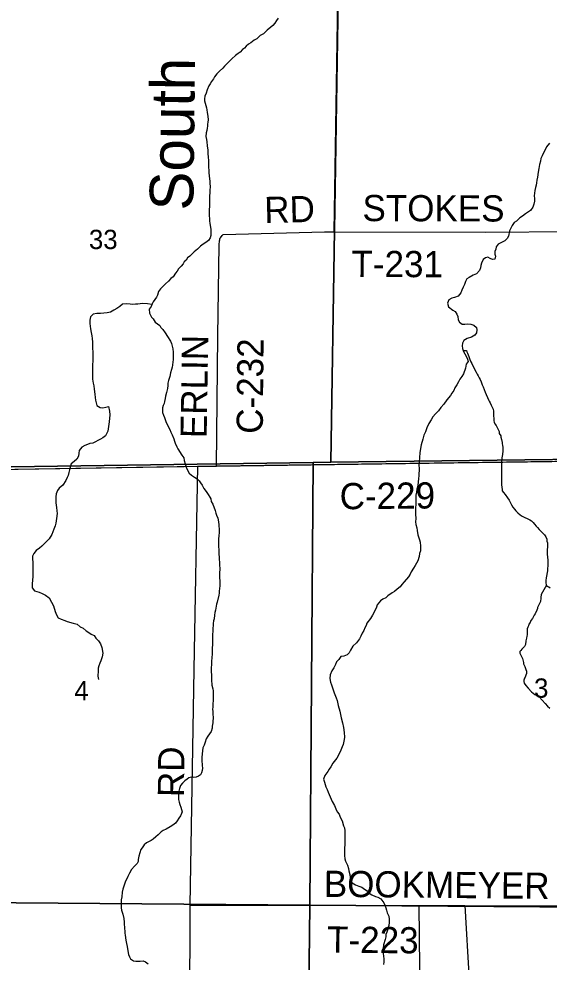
# Model space of a CAD drawing. Extents: x -8.5 to 18.7, y -20.3 to 7.
# Drawn here: x 4.267 to 6.568, y -1.005 to 3.087 of the extents above; entities that cross this region are included whole.
import ezdxf

# ---------------------------------------------------------------- set-up
doc = ezdxf.new("R2010")
doc.units = 0
for name, color, linetype in [('GM_X_Corporation', 7, 'Continuous'), ('GM_X_County_Road', 7, 'Continuous'), ('GM_X_County_Road_Text', 7, 'Continuous'), ('GM_X_Minor_River', 7, 'Continuous'), ('GM_X_Minor_River_Text', 7, 'Continuous'), ('GM_X_Section', 7, 'Continuous'), ('GM_X_Section_Text', 7, 'Continuous'), ('GM_X_Township', 7, 'Continuous'), ('GM_X_Township_Road', 7, 'Continuous'), ('GM_X_Township_Road_Text', 7, 'Continuous')]:
    doc.layers.add(name, color=color, linetype=linetype)

msp = doc.modelspace()

# ---------------------------------------------------------------- linework, layer by layer
at = {"layer": 'GM_X_Corporation'}
for points in [[(3.6318, 1.1236), (5.043, 1.1473), (5.1251, 1.1484), (7.5383, 1.181), (7.59, 1.1818), (9.5569, 1.2131), (11.5871, 1.2389), (11.6132, 2.2462), (11.64, 3.2551), (11.6653, 4.2586), (11.6686, 4.5917), (11.6689, 4.6186), (11.6732, 5.0475), (11.7049, 6.938), (-0.1911, 6.938)], [(6.0195, -2.1051), (6.0042, -0.7588), (6.2025, -0.7592), (6.2213, -1.0838)]]:
    msp.add_lwpolyline(points, dxfattribs=at)
at = {"layer": 'GM_X_County_Road'}
for p, q in [((4.9846, 1.1452), (5.0434, 1.1462)), ((5.0285, 0.2644), (5.0434, 1.1462)), ((5.0434, 1.1462), (5.1255, 1.1473)), ((5.1255, 1.1473), (6.0476, 1.1597)), ((3.6322, 1.1225), (4.9846, 1.1452))]:
    msp.add_line(p, q, dxfattribs=at)
for points in [[(5.1255, 1.1473), (5.1307, 1.71), (5.1363, 2.1065), (5.1381, 2.1247), (5.1389, 2.1285), (5.1398, 2.1338), (5.1421, 2.1376), (5.1491, 2.1474), (5.1537, 2.1511), (5.5936, 2.163), (5.6353, 2.1639), (5.6522, 3.168), (5.6659, 4.3348)], [(6.0476, 1.1597), (7.5387, 1.1799), (7.5905, 1.1807)], [(5.0013, -1.7027), (5.0019, -1.6852), (5.0045, -1.5114), (5.0068, -1.3109), (5.0093, -1.0879), (5.0109, -0.8927), (5.0112, -0.7576), (5.0285, 0.2644)]]:
    msp.add_lwpolyline(points, dxfattribs=at)
at = {"layer": 'GM_X_Minor_River'}
for points in [[(5.3929, 3.0899), (5.3852, 3.0801), (5.3783, 3.0688), (5.3698, 3.0582), (5.3606, 3.0515), (5.3445, 3.0387), (5.3292, 3.023), (5.3147, 3.0148), (5.3001, 3.0005), (5.2879, 2.9953), (5.2741, 2.9841), (5.2634, 2.9781), (5.2535, 2.9684), (5.2465, 2.9601), (5.2374, 2.9549), (5.2281, 2.9428), (5.219, 2.9376), (5.2075, 2.9286), (5.1921, 2.9136), (5.1791, 2.9016), (5.1707, 2.8933), (5.1599, 2.882), (5.1522, 2.8738), (5.1377, 2.8603), (5.1269, 2.8482), (5.1169, 2.8362), (5.1123, 2.8279), (5.1038, 2.8151), (5.0976, 2.806), (5.0922, 2.7962), (5.0851, 2.7788), (5.0804, 2.7652), (5.0742, 2.7516), (5.0726, 2.741), (5.0725, 2.7319), (5.0791, 2.7113), (5.0812, 2.7014), (5.0826, 2.6923), (5.0848, 2.6817), (5.0876, 2.6657), (5.0882, 2.6497), (5.0873, 2.6391), (5.0865, 2.63), (5.0856, 2.6217), (5.0848, 2.6126), (5.0824, 2.6035), (5.08, 2.5929), (5.0791, 2.5777), (5.0812, 2.5633), (5.0826, 2.5534), (5.0839, 2.5367), (5.0875, 2.5184), (5.0881, 2.5047), (5.0894, 2.4865), (5.09, 2.4743), (5.0898, 2.4523), (5.0904, 2.4417), (5.0911, 2.4318), (5.0917, 2.4189), (5.093, 2.406), (5.0944, 2.3938), (5.0958, 2.3839), (5.0964, 2.3718), (5.0971, 2.3619), (5.0968, 2.3414), (5.096, 2.3323), (5.0951, 2.3194), (5.0949, 2.3012), (5.094, 2.2913), (5.0934, 2.2427), (5.0946, 2.2108), (5.096, 2.1994), (5.1003, 2.1751), (5.1009, 2.1652)], [(6.5695, 2.5481), (6.5572, 2.5322), (6.5494, 2.5156), (6.544, 2.5058), (6.5378, 2.4937), (6.5331, 2.4809), (6.5307, 2.4703), (6.5267, 2.4559), (6.5235, 2.4377), (6.521, 2.4218)], [(6.521, 2.4218), (6.5178, 2.4006), (6.5153, 2.3877), (6.5137, 2.3763), (6.5121, 2.3665), (6.5089, 2.3559), (6.5057, 2.3422), (6.5048, 2.3316), (6.5039, 2.3202), (6.5046, 2.3073), (6.5044, 2.2967), (6.502, 2.2838), (6.4973, 2.2702), (6.4873, 2.2566), (6.4659, 2.2409), (6.4529, 2.2312), (6.4406, 2.2245), (6.4268, 2.2095), (6.4161, 2.2035), (6.4084, 2.1914), (6.4014, 2.1771), (6.3967, 2.1673), (6.3919, 2.1453), (6.3865, 2.134), (6.3758, 2.125), (6.3582, 2.1153), (6.3475, 2.1101), (6.3383, 2.0988), (6.3367, 2.0889), (6.3328, 2.0776), (6.3326, 2.067), (6.3363, 2.0571), (6.3331, 2.0449), (6.3233, 2.0435), (6.3127, 2.0474), (6.3021, 2.0529), (6.2922, 2.0499), (6.2823, 2.044), (6.2745, 2.0273), (6.2714, 2.0168), (6.2705, 2.0069), (6.2666, 1.9963), (6.2528, 1.9813), (6.239, 1.9753), (6.2215, 1.9657), (6.2108, 1.9589), (6.2053, 1.9484), (6.2014, 1.9355), (6.196, 1.9234), (6.1897, 1.9106), (6.185, 1.8985), (6.1735, 1.8849), (6.1583, 1.8783), (6.1461, 1.8754), (6.1331, 1.8687), (6.1269, 1.8536), (6.1313, 1.8383), (6.15, 1.8229), (6.1606, 1.8175), (6.1681, 1.8068), (6.1717, 1.7961), (6.1738, 1.7809), (6.1798, 1.771), (6.1911, 1.7633), (6.2032, 1.7631), (6.2139, 1.7646), (6.229, 1.7629), (6.2419, 1.7589), (6.2539, 1.7482), (6.2553, 1.7383), (6.2529, 1.7247), (6.2459, 1.7149), (6.2314, 1.7067), (6.2124, 1.7008), (6.1986, 1.6918), (6.1924, 1.6797), (6.1915, 1.6691), (6.1929, 1.6577), (6.1973, 1.644), (6.2033, 1.6341), (6.2077, 1.6242), (6.2144, 1.6104), (6.2165, 1.6005), (6.2088, 1.5885), (6.2048, 1.5718), (6.197, 1.5476), (6.1893, 1.5355), (6.1815, 1.5242), (6.1746, 1.5129), (6.1684, 1.4993), (6.1591, 1.4865), (6.1544, 1.4752), (6.1467, 1.4631), (6.1405, 1.4533), (6.1244, 1.4345), (6.1113, 1.4156), (6.0989, 1.4006), (6.0882, 1.3863), (6.0759, 1.3735), (6.0644, 1.3607), (6.0559, 1.3479)], [(5.1009, 2.1652), (5.1008, 2.1569), (5.1007, 2.147), (5.0976, 2.1372), (5.0906, 2.1251), (5.0791, 2.1176), (5.0669, 2.1094), (5.0562, 2.1012), (5.0431, 2.0876), (5.0286, 2.0764), (5.0202, 2.0697), (5.0087, 2.0584), (4.9995, 2.0501), (4.994, 2.0403), (4.9848, 2.0336), (4.9802, 2.0245), (4.9717, 2.014), (4.9602, 2.0027), (4.9548, 1.9929), (4.9471, 1.9839), (4.9363, 1.9688), (4.9271, 1.9613), (4.9164, 1.95), (4.9041, 1.9373), (4.8926, 1.926), (4.8826, 1.9155), (4.8734, 1.9042), (4.8686, 1.8883), (4.8647, 1.88), (4.8509, 1.8596), (4.8454, 1.8506), (4.8415, 1.84), (4.833, 1.8272), (4.8344, 1.8105), (4.8425, 1.7937), (4.85, 1.7852), (4.859, 1.7715), (4.8785, 1.7568), (4.8837, 1.7477), (4.892, 1.7392), (4.9024, 1.7255), (4.9129, 1.7086), (4.9248, 1.6888), (4.9292, 1.6789), (4.9329, 1.6674), (4.9358, 1.6553), (4.9371, 1.6408), (4.9368, 1.6082), (4.9359, 1.5998), (4.9342, 1.5854), (4.9326, 1.5763), (4.9302, 1.5657), (4.9255, 1.5514), (4.9223, 1.5362), (4.9168, 1.5188), (4.9144, 1.5067), (4.9135, 1.4968), (4.9118, 1.4839), (4.9086, 1.4657), (4.9038, 1.4506), (4.9022, 1.4408), (4.8998, 1.4279), (4.8974, 1.4188), (4.8935, 1.4097), (4.8904, 1.3991), (4.8909, 1.3794), (4.8946, 1.368), (4.8998, 1.358), (4.9049, 1.3398), (4.9116, 1.3275), (4.9219, 1.3062), (4.9271, 1.2947), (4.933, 1.2825), (4.9397, 1.2657), (4.9433, 1.2551), (4.9463, 1.2459), (4.9529, 1.2307), (4.9566, 1.2215), (4.9745, 1.194), (4.9827, 1.1833), (4.9849, 1.1711), (4.9893, 1.1574), (4.9914, 1.1483), (4.9951, 1.1383), (5.007, 1.117), (5.016, 1.1078), (5.0296, 1.0985), (5.0409, 1.0915), (5.0491, 1.0831), (5.0551, 1.0747), (5.0626, 1.064), (5.0707, 1.0502), (5.0805, 1.0372), (5.0894, 1.0242), (5.0961, 1.0128), (5.1006, 1.0044), (5.102, 0.9937), (5.1094, 0.9815), (5.119, 0.9541), (5.1219, 0.9426), (5.1256, 0.9335)], [(4.8443, 1.8475), (4.825, 1.8516), (4.8037, 1.8518), (4.784, 1.8497), (4.7733, 1.8491), (4.762, 1.8477), (4.7506, 1.8493), (4.7362, 1.851), (4.7172, 1.8489), (4.705, 1.8392), (4.6927, 1.831), (4.6797, 1.8235), (4.6645, 1.8153), (4.65, 1.8117), (4.6363, 1.8103), (4.6212, 1.809), (4.606, 1.8084), (4.5893, 1.8063), (4.5785, 1.7942), (4.5753, 1.7806), (4.5759, 1.7654), (4.5787, 1.7426), (4.5815, 1.7259), (4.5836, 1.7122), (4.585, 1.7008), (4.5864, 1.6848), (4.5876, 1.6643), (4.5888, 1.6362), (4.5879, 1.6225), (4.5877, 1.6043), (4.5868, 1.5861), (4.5863, 1.5444), (4.5876, 1.5238), (4.5896, 1.5064), (4.5926, 1.4957), (4.5947, 1.4813), (4.5967, 1.4592), (4.5988, 1.444), (4.6002, 1.4326), (4.6023, 1.4212), (4.6052, 1.4098), (4.6203, 1.4013), (4.6324, 1.4004), (4.6454, 1.4025), (4.656, 1.4054), (4.6611, 1.3856), (4.6624, 1.3689), (4.659, 1.3386), (4.6533, 1.2992), (4.6486, 1.2894), (4.6439, 1.2788), (4.6317, 1.2698), (4.6218, 1.2631), (4.5882, 1.2467), (4.576, 1.2446), (4.5646, 1.2409), (4.5539, 1.2357), (4.5402, 1.229), (4.5294, 1.2147), (4.5278, 1.2033), (4.5261, 1.1897), (4.5184, 1.1769), (4.5076, 1.1664), (4.4946, 1.1574), (4.4875, 1.1301), (4.4843, 1.1188), (4.4819, 1.1067), (4.4772, 1.0968), (4.471, 1.084), (4.4587, 1.0644), (4.4426, 1.0516), (4.4349, 1.0411), (4.4286, 1.026), (4.4277, 1.0131), (4.4276, 1.0009), (4.4282, 0.9873), (4.431, 0.9667), (4.4316, 0.9531), (4.433, 0.9417), (4.4312, 0.9189), (4.428, 0.9), (4.4255, 0.8871), (4.4193, 0.8727), (4.4146, 0.8621), (4.4107, 0.85), (4.3991, 0.8319), (4.3876, 0.8199), (4.3768, 0.8094), (4.3676, 0.7996), (4.3577, 0.7914), (4.3431, 0.7809), (4.3324, 0.7681), (4.3269, 0.7568), (4.326, 0.7439), (4.3274, 0.7287), (4.3279, 0.7074), (4.3274, 0.668), (4.3248, 0.6361), (4.3254, 0.6194), (4.3351, 0.6056), (4.3555, 0.5993)], [(6.1957, 1.649), (6.2098, 1.6488), (6.2114, 1.6427), (6.2145, 1.6366), (6.2198, 1.623), (6.2237, 1.6101), (6.2283, 1.5995), (6.2329, 1.5919), (6.236, 1.5851), (6.2421, 1.5752), (6.2467, 1.5646), (6.2521, 1.5548), (6.2567, 1.5464), (6.2605, 1.5388), (6.2651, 1.5305), (6.2689, 1.5229), (6.2728, 1.5123), (6.2782, 1.5002), (6.2828, 1.4903), (6.2866, 1.4789), (6.2912, 1.4683), (6.2958, 1.457), (6.3012, 1.4448), (6.3051, 1.435), (6.3081, 1.4281), (6.312, 1.4213), (6.3166, 1.4107), (6.3212, 1.4024), (6.325, 1.394), (6.3266, 1.3849), (6.3274, 1.3758), (6.3274, 1.3637), (6.3282, 1.3546), (6.3291, 1.3439), (6.3306, 1.3378), (6.3329, 1.331), (6.3383, 1.3227), (6.3459, 1.309), (6.3513, 1.2977), (6.3521, 1.2886), (6.3582, 1.278), (6.359, 1.2726), (6.3614, 1.262), (6.3645, 1.2491), (6.3653, 1.243), (6.366, 1.2377), (6.3669, 1.2271), (6.3676, 1.2218), (6.3677, 1.2134), (6.3655, 1.1975), (6.3633, 1.1823), (6.3618, 1.1655), (6.3612, 1.1526), (6.362, 1.1351), (6.3613, 1.1275), (6.3613, 1.1207), (6.3621, 1.1108), (6.3622, 1.104), (6.3615, 1.0827), (6.3616, 1.066), (6.364, 1.0455), (6.3648, 1.0394), (6.3709, 1.0326), (6.377, 1.0243), (6.3877, 1.0091), (6.3946, 0.9985), (6.3992, 0.9902), (6.4045, 0.9796), (6.4114, 0.969), (6.4183, 0.9599), (6.4237, 0.9531), (6.4321, 0.9448), (6.4427, 0.9357), (6.4519, 0.9297), (6.4625, 0.9244), (6.4724, 0.9191), (6.4846, 0.9131), (6.4914, 0.9094), (6.4991, 0.9026), (6.5052, 0.8957), (6.5121, 0.8867), (6.5182, 0.8806), (6.5258, 0.8723), (6.535, 0.8617), (6.5426, 0.8541), (6.5487, 0.8488), (6.554, 0.8405), (6.5579, 0.8299), (6.5587, 0.8215), (6.561, 0.8147), (6.5611, 0.7965), (6.5596, 0.7836), (6.5597, 0.7744), (6.5605, 0.7653), (6.5613, 0.7524), (6.5622, 0.7388), (6.5623, 0.7129), (6.5616, 0.7038), (6.5608, 0.6985), (6.5609, 0.6932), (6.5594, 0.6848)], [(6.0559, 1.3479), (6.0458, 1.3313), (6.0373, 1.3124), (6.0317, 1.295), (6.0247, 1.2807), (6.0208, 1.264), (6.0137, 1.2398), (6.0097, 1.2239), (6.0072, 1.2049), (6.0054, 1.1837), (6.0045, 1.1647), (6.0035, 1.1488), (6.0042, 1.1389), (6.004, 1.126), (6.0031, 1.1162), (6.003, 1.104), (6.0021, 1.0941), (5.9996, 1.076), (5.9988, 1.0661), (5.9971, 1.0562), (5.9948, 1.0464), (5.9931, 1.0335), (5.9907, 1.0214), (5.9898, 1.0085), (5.989, 0.9379), (5.9895, 0.9197), (5.9886, 0.9052), (5.99, 0.8938), (5.9936, 0.8794), (5.9958, 0.868), (5.9993, 0.8489), (6.0059, 0.8269), (6.0088, 0.817), (6.0109, 0.7995), (6.0099, 0.779), (6.006, 0.7676), (6.0043, 0.7548), (5.9988, 0.7366), (5.9864, 0.7155), (5.9802, 0.7034), (5.9702, 0.6875), (5.9648, 0.6777), (5.9586, 0.6664), (5.9393, 0.6446), (5.9294, 0.6333), (5.9224, 0.6228), (5.9086, 0.613), (5.8979, 0.6033), (5.8872, 0.5966), (5.8681, 0.5846), (5.8596, 0.5748), (5.8474, 0.5689), (5.8367, 0.5622), (5.8229, 0.5456), (5.819, 0.535), (5.8151, 0.5252), (5.8019, 0.5003), (5.7934, 0.4852), (5.778, 0.4656), (5.7741, 0.4551), (5.7686, 0.4452), (5.764, 0.4339), (5.7578, 0.4218), (5.7508, 0.4097), (5.7453, 0.3977), (5.7322, 0.3796), (5.7161, 0.3661), (5.7068, 0.3487), (5.7014, 0.3366), (5.6914, 0.3276), (5.6777, 0.3225), (5.6648, 0.3211), (5.6563, 0.3075), (5.6456, 0.297), (5.6409, 0.2864), (5.6347, 0.2721), (5.6254, 0.2593), (5.6176, 0.2411), (5.6174, 0.2259), (5.6195, 0.21), (5.6239, 0.1978), (5.6291, 0.181), (5.6357, 0.1635), (5.6446, 0.1421), (5.6482, 0.1299), (5.6533, 0.1079), (5.6606, 0.0835), (5.6663, 0.0553), (5.6721, 0.0325), (5.6765, 0.0135), (5.6785, -0.0086), (5.6805, -0.0291), (5.6789, -0.0397), (5.6749, -0.0609), (5.6702, -0.0707), (5.6647, -0.0859), (5.6585, -0.0979), (5.6469, -0.1198), (5.6299, -0.1424), (5.6214, -0.1575), (5.6145, -0.1681)], [(5.1256, 0.9335), (5.1315, 0.9205), (5.1336, 0.9045), (5.1349, 0.8916), (5.1362, 0.8696), (5.1361, 0.8582), (5.1352, 0.8445), (5.1343, 0.8316), (5.1339, 0.7975), (5.1345, 0.7838), (5.135, 0.7656), (5.1364, 0.7511), (5.137, 0.742), (5.1376, 0.7299), (5.1383, 0.717), (5.1389, 0.7025), (5.1378, 0.6805), (5.1384, 0.6615), (5.139, 0.6486), (5.1396, 0.6388), (5.1395, 0.6274), (5.1386, 0.6152), (5.137, 0.6046), (5.1361, 0.5955), (5.1345, 0.5864), (5.1273, 0.5569), (5.1249, 0.5478), (5.1233, 0.5395), (5.1217, 0.5311), (5.1201, 0.5213), (5.1185, 0.5122), (5.1161, 0.5008), (5.1144, 0.4849), (5.1127, 0.4758), (5.1111, 0.4637), (5.1102, 0.4546), (5.1094, 0.4447), (5.1085, 0.4356), (5.1084, 0.4273), (5.1075, 0.4189), (5.1073, 0.3946), (5.1079, 0.3817), (5.1077, 0.3703), (5.1069, 0.3597), (5.106, 0.3461), (5.1058, 0.3354), (5.1041, 0.3127), (5.1032, 0.3036), (5.1026, 0.2542), (5.1032, 0.2406), (5.103, 0.2193), (5.105, 0.1965), (5.1086, 0.1805), (5.11, 0.1722), (5.1112, 0.1448), (5.1111, 0.1319), (5.1094, 0.1145), (5.1085, 0.1016), (5.1076, 0.0917), (5.109, 0.0826), (5.1097, 0.0742), (5.1102, 0.053), (5.1093, 0.0408), (5.1092, 0.0325), (5.1068, 0.0188), (5.1059, 0.0105), (5.1012, -0.0046), (5.095, -0.0144), (5.0873, -0.025), (5.0803, -0.0363), (5.0756, -0.0507), (5.0709, -0.0635), (5.0662, -0.0756), (5.0646, -0.0885), (5.0612, -0.1158), (5.0618, -0.1295), (5.0631, -0.1515), (5.0637, -0.1637), (5.0628, -0.1743), (5.0605, -0.1834), (5.0558, -0.1924), (5.0466, -0.1984), (5.0367, -0.2021), (5.0253, -0.2035), (5.017, -0.2034), (5.0056, -0.2063), (4.9972, -0.2116), (4.9872, -0.2183), (4.978, -0.228), (4.9695, -0.2393), (4.9641, -0.2514), (4.9609, -0.2628), (4.96, -0.278), (4.9599, -0.2878), (4.9605, -0.2992), (4.9626, -0.3114), (4.9656, -0.3213), (4.97, -0.3335), (4.9737, -0.3426), (4.9758, -0.3525), (4.9735, -0.3609)], [(6.5594, 0.6848), (6.5564, 0.6696), (6.5557, 0.6627), (6.5542, 0.6506), (6.5543, 0.6384), (6.5551, 0.6331), (6.5589, 0.6263), (6.5665, 0.6225), (6.5734, 0.6188)], [(6.5569, 0.6299), (6.5342, 0.5899), (6.5331, 0.577), (6.5322, 0.5694), (6.5306, 0.5641), (6.5305, 0.5588), (6.5273, 0.5506), (6.5186, 0.534), (6.5177, 0.5287), (6.5146, 0.5212), (6.5082, 0.5054), (6.5035, 0.5002), (6.4956, 0.4852), (6.4894, 0.4777), (6.4854, 0.4687), (6.4807, 0.4612), (6.4791, 0.4544), (6.4759, 0.4484), (6.4735, 0.4409), (6.4726, 0.4356), (6.4724, 0.4227), (6.473, 0.4151), (6.4721, 0.4098), (6.4704, 0.4), (6.4679, 0.3894), (6.4653, 0.3727), (6.4613, 0.3645), (6.4551, 0.3585), (6.4497, 0.3533), (6.4451, 0.3473), (6.4419, 0.3421), (6.441, 0.3353), (6.449, 0.3207), (6.4534, 0.3115), (6.4576, 0.2947), (6.4575, 0.2894), (6.4625, 0.2772), (6.4676, 0.2642), (6.4697, 0.2566), (6.4702, 0.2475), (6.4678, 0.2399), (6.4638, 0.2317), (6.4622, 0.2264), (6.459, 0.2181), (6.4582, 0.2128), (6.4595, 0.2052), (6.4669, 0.1952), (6.4772, 0.1828), (6.4913, 0.1681), (6.507, 0.1564), (6.5249, 0.1455), (6.5516, 0.1176), (6.5619, 0.1053), (6.5708, 0.0968)], [(4.3555, 0.5993), (4.3691, 0.5946), (4.3834, 0.5876), (4.3992, 0.5761), (4.4096, 0.5562), (4.4178, 0.5402), (4.4251, 0.5166), (4.431, 0.5021), (4.4384, 0.4891), (4.4505, 0.4822), (4.4671, 0.4767), (4.4769, 0.472), (4.5034, 0.4656), (4.5201, 0.4617), (4.5328, 0.4501), (4.5464, 0.4439), (4.5599, 0.4316), (4.5712, 0.4254), (4.5818, 0.4177), (4.5938, 0.4115), (4.6021, 0.4001), (4.6126, 0.3893), (4.6223, 0.3763), (4.6274, 0.3603), (4.6317, 0.336), (4.6292, 0.32), (4.6229, 0.3019), (4.619, 0.2921), (4.6143, 0.2807), (4.612, 0.2709), (4.6111, 0.2587), (4.6108, 0.2352), (4.6133, 0.2214)], [(5.6145, -0.1681), (5.6083, -0.1779), (5.5944, -0.1959), (5.5897, -0.2118), (5.5933, -0.2248), (5.5992, -0.2453), (5.6051, -0.256), (5.6095, -0.2682), (5.6176, -0.288), (5.6273, -0.3079), (5.6369, -0.3262), (5.6428, -0.3399), (5.648, -0.3529), (5.6577, -0.3636), (5.6622, -0.3758), (5.6703, -0.3926), (5.6761, -0.4132), (5.6798, -0.4231), (5.6812, -0.436), (5.6818, -0.4474), (5.6814, -0.4823), (5.682, -0.4975), (5.6811, -0.5074), (5.6807, -0.5431), (5.6813, -0.5567), (5.6843, -0.5666), (5.6932, -0.5842), (5.6975, -0.5994), (5.6997, -0.6093), (5.7041, -0.6253), (5.7054, -0.6375), (5.7061, -0.6481), (5.7143, -0.6611), (5.7278, -0.6703), (5.7422, -0.6751), (5.755, -0.6797), (5.7678, -0.689), (5.7784, -0.6952), (5.7881, -0.7059), (5.7987, -0.7129), (5.8153, -0.7206), (5.8251, -0.723), (5.8387, -0.7307), (5.8506, -0.7483), (5.8558, -0.7583), (5.8595, -0.7689), (5.8631, -0.7804), (5.866, -0.791), (5.8727, -0.8063), (5.8748, -0.8192), (5.8747, -0.8329), (5.873, -0.8458), (5.8683, -0.8616), (5.8643, -0.8745), (5.8597, -0.8851), (5.8595, -0.895), (5.8564, -0.9071), (5.85, -0.9305), (5.8476, -0.9457), (5.8482, -0.9578), (5.8488, -0.9677), (5.8509, -0.9913), (5.8507, -1.0034), (5.8498, -1.0148)], [(4.9735, -0.3609), (4.9688, -0.3707), (4.9619, -0.3805), (4.9549, -0.3925), (4.9472, -0.4023), (4.9349, -0.4113), (4.9242, -0.418), (4.9067, -0.4285), (4.8937, -0.4344), (4.8853, -0.4404), (4.8723, -0.4524), (4.8615, -0.4621), (4.85, -0.4719), (4.8416, -0.4779), (4.8325, -0.4823), (4.821, -0.4883), (4.8111, -0.4958), (4.8018, -0.5086), (4.7972, -0.5169), (4.7925, -0.5312), (4.7878, -0.5449), (4.7853, -0.5593), (4.7852, -0.5684), (4.7806, -0.5774), (4.769, -0.5895), (4.7567, -0.603), (4.7475, -0.6196), (4.7397, -0.6339), (4.7358, -0.6445), (4.7304, -0.6543), (4.7249, -0.6717), (4.7186, -0.6884), (4.7154, -0.7012), (4.7137, -0.7217), (4.712, -0.7346), (4.711, -0.7543), (4.7108, -0.7695), (4.7122, -0.7802), (4.7181, -0.7977), (4.7224, -0.8159), (4.7238, -0.8311), (4.7244, -0.8433), (4.7251, -0.8517), (4.7257, -0.8608), (4.7271, -0.8699), (4.7278, -0.879), (4.7292, -0.8881), (4.732, -0.9094), (4.7349, -0.9246), (4.737, -0.9376), (4.7406, -0.9566), (4.7434, -0.9726), (4.7479, -0.9825), (4.7516, -0.9909), (4.7643, -0.9994), (4.7757, -1.001), (4.7848, -1.0011), (4.7939, -1.0004), (4.8068, -0.9998), (4.8166, -1.0045), (4.8287, -1.0122)]]:
    msp.add_lwpolyline(points, dxfattribs=at)
at = {"layer": 'GM_X_Section'}
for points in [[(7.6532, 3.1997), (7.5973, 1.189), (7.5458, 1.1869), (5.621, 1.1642), (5.6525, 3.1789)], [(5.6525, 3.1789), (5.621, 1.1642), (5.5445, 1.1632), (3.628, 1.1349), (3.6457, 3.1367)], [(7.5458, 1.1869), (7.5243, -0.7725), (5.5303, -0.7575), (5.5445, 1.1632), (5.621, 1.1642)], [(5.5445, 1.1632), (5.5303, -0.7575), (3.5254, -0.7421), (3.5552, 1.1316), (3.628, 1.1349)], [(5.5303, -0.7575), (5.5072, -2.7563), (3.5091, -2.759), (3.5254, -0.7421)], [(7.5243, -0.7725), (7.4906, -2.7325), (5.5072, -2.7563), (5.5303, -0.7575)]]:
    msp.add_lwpolyline(points, close=True, dxfattribs=at)
at = {"layer": 'GM_X_Township'}
msp.add_lwpolyline([(3.6318, 1.1236), (5.043, 1.1473), (5.1251, 1.1484), (7.5383, 1.181), (7.59, 1.1818), (9.5569, 1.2131), (11.5871, 1.2389), (11.5625, -0.7587), (11.5622, -0.7805), (11.5527, -2.1798)], dxfattribs=at)
at = {"layer": 'GM_X_Township_Road'}
for p, q in [((5.0112, -0.7576), (6.0047, -0.7599)), ((6.0047, -0.7599), (6.203, -0.7603)), ((6.203, -0.7603), (7.5325, -0.7633))]:
    msp.add_line(p, q, dxfattribs=at)
msp.add_lwpolyline([(5.6353, 2.1639), (6.2929, 2.1617), (6.6703, 2.1655), (6.924, 2.1827), (7.6182, 2.1915)], dxfattribs=at)

# ---------------------------------------------------------------- texts
at = {"layer": 'GM_X_County_Road_Text'}
for s, rotation, p in [('RD', 1.4816, (5.3337, 2.2011)), ('ERLIN', 89.0651, (5.0822, 1.2676)), ('C-232', 89.4494, (5.3256, 1.2866)), ('C-229', 0.5511, (5.66, 0.9594)), ('RD', 89.5063, (4.9839, -0.2894))]:
    msp.add_text(s, height=0.11364, rotation=rotation, dxfattribs=at).set_placement(p)
at = {"layer": 'GM_X_Minor_River_Text'}
msp.add_text('South', height=0.18951, rotation=89.2649, dxfattribs=at).set_placement((5.0238, 2.2549))
at = {"layer": 'GM_X_Section_Text'}
for s, height, p in [('33', 0.08371, (4.5715, 2.0886)), ('4', 0.0837, (4.5081, 0.1309)), ('3', 0.0837, (6.5031, 0.142))]:
    msp.add_text(s, height=height, rotation=0, dxfattribs=at).set_placement(p)
at = {"layer": 'GM_X_Township_Road_Text'}
for s, rotation, p in [('STOKES', 359.8182, (5.7583, 2.2099)), ('T-231', 359.7193, (5.7105, 1.968)), ('BOOKMEYER', 359.4573, (5.5903, -0.7218)), ('T-223', 359.4381, (5.6045, -0.9637))]:
    msp.add_text(s, height=0.11364, rotation=rotation, dxfattribs=at).set_placement(p)

doc.saveas('drawing.dxf')
